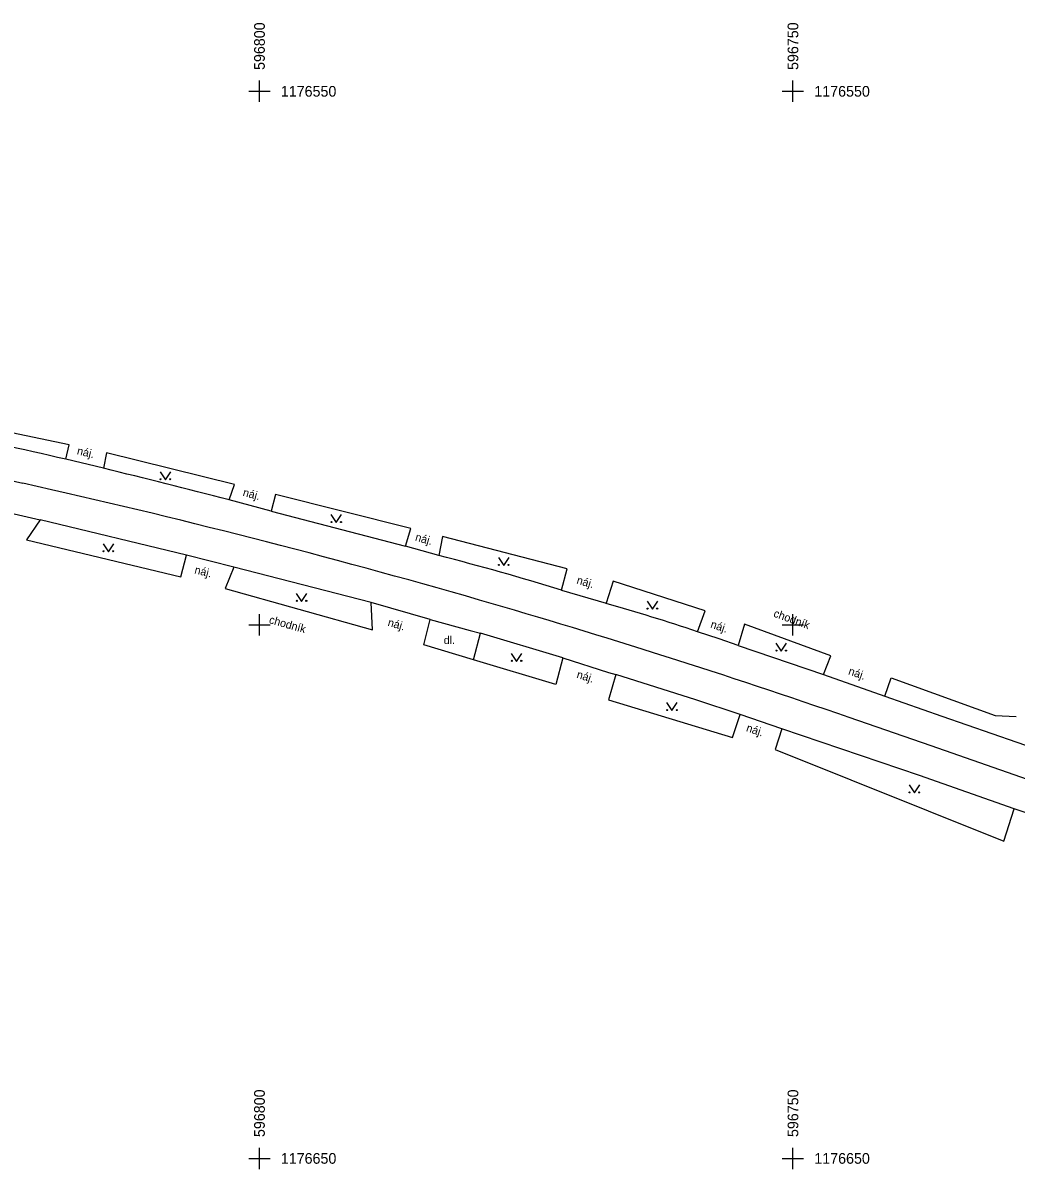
# Model space of a CAD drawing. Extents: x -598160 to -596067, y -1177005 to -1176344.
# Drawn here: x -596822.2 to -596729.1, y -1176651 to -1176543.6 of the extents above; entities that cross this region are included whole.
import ezdxf

# ---------------------------------------------------------------- set-up
doc = ezdxf.new("R2010")
doc.units = 0
for name, color, linetype in [('hektametrová síť', 7, 'Continuous'), ('obruba +0 cm', 7, 'Continuous'), ('obruba +12 cm', 7, 'Continuous'), ('obruba +3 cm', 7, 'Continuous'), ('popis ploch', 7, 'Continuous'), ('rozhraní ploch', 7, 'Continuous'), ('vodorovné značení', 7, 'Continuous'), ('zeleň', 7, 'Continuous')]:
    doc.layers.add(name, color=color, linetype=linetype)

msp = doc.modelspace()

# ---------------------------------------------------------------- linework, layer by layer
at = {"layer": 'hektametrová síť'}
for p, q in [((-596800, -1176551), (-596800, -1176549)), ((-596750, -1176551), (-596750, -1176549)), ((-596801, -1176550), (-596799, -1176550)), ((-596751, -1176550), (-596749, -1176550)), ((-596800, -1176601), (-596800, -1176599)), ((-596750, -1176601), (-596750, -1176599)), ((-596801, -1176600), (-596799, -1176600)), ((-596751, -1176600), (-596749, -1176600)), ((-596800, -1176651), (-596800, -1176649)), ((-596750, -1176651), (-596750, -1176649)), ((-596801, -1176650), (-596799, -1176650)), ((-596751, -1176650), (-596749, -1176650))]:
    msp.add_line(p, q, dxfattribs=at)
at = {"layer": 'obruba +0 cm'}
for p, q in [((-596814.63, -1176585.31), (-596818.16, -1176584.48)), ((-596798.9, -1176589.34), (-596802.85, -1176588.28)), ((-596823, -1176589.61), (-596820.54, -1176590.16)), ((-596783.18, -1176593.51), (-596786.32, -1176592.62)), ((-596802.39, -1176594.58), (-596806.83, -1176593.47)), ((-596784.01, -1176599.49), (-596789.54, -1176597.89)), ((-596771.57, -1176603.1), (-596767.28, -1176604.45)), ((-596767.28, -1176604.45), (-596766.59, -1176604.66)), ((-596747.13, -1176604.66), (-596741.39, -1176606.67))]:
    msp.add_line(p, q, dxfattribs=at)
at = {"layer": 'obruba +12 cm'}
for p, q in [((-596798.9, -1176589.34), (-596786.32, -1176592.62)), ((-596806.83, -1176593.47), (-596820.54, -1176590.16)), ((-596789.54, -1176597.89), (-596802.39, -1176594.58)), ((-596771.57, -1176603.1), (-596779.28, -1176600.79)), ((-596755.14, -1176601.93), (-596747.13, -1176604.66)), ((-596759.11, -1176607.03), (-596766.59, -1176604.66)), ((-596754.96, -1176608.39), (-596759.11, -1176607.03)), ((-596741.39, -1176606.67), (-596736.04, -1176608.55)), ((-596736.04, -1176608.55), (-596715.72, -1176615.6)), ((-596738.13, -1176614.11), (-596751.03, -1176609.73)), ((-596729.28, -1176617.25), (-596738.13, -1176614.11))]:
    msp.add_line(p, q, dxfattribs=at)
for centre, radius, start, end in [((-596922.01, -1177032.53), 459.93, 76.9505, 78.5161), ((-597174.08, -1178035.85), 1494.41, 75.61648, 76.08226), ((-596851.03, -1176856.68), 271.78, 73.0284, 75.5428), ((-596828.43, -1176808.89), 219.53, 71.5499, 73.8871)]:
    msp.add_arc(centre, radius, start, end, dxfattribs=at)
at = {"layer": 'obruba +3 cm'}
for p, q in [((-596771.7, -1176596.74), (-596767.5, -1176597.98)), ((-596784.01, -1176599.49), (-596780.26, -1176600.52)), ((-596780.26, -1176600.52), (-596779.28, -1176600.79)), ((-596756.93, -1176601.31), (-596758.95, -1176600.64)), ((-596755.14, -1176601.93), (-596756.93, -1176601.31)), ((-596751.03, -1176609.73), (-596754.96, -1176608.39)), ((-596725.43, -1176618.55), (-596729.28, -1176617.25))]:
    msp.add_line(p, q, dxfattribs=at)
at = {"layer": 'rozhraní ploch'}
for p, q in [((-596817.83, -1176583.12), (-596830.31, -1176580.53)), ((-596818.16, -1176584.48), (-596817.83, -1176583.12)), ((-596814.33, -1176583.89), (-596814.63, -1176585.31)), ((-596802.34, -1176586.85), (-596814.33, -1176583.89)), ((-596802.85, -1176588.28), (-596802.34, -1176586.85)), ((-596798.51, -1176587.79), (-596798.9, -1176589.34)), ((-596785.82, -1176590.97), (-596798.51, -1176587.79)), ((-596820.54, -1176590.16), (-596821.83, -1176592.03)), ((-596786.32, -1176592.62), (-596785.82, -1176590.97)), ((-596821.83, -1176592.03), (-596807.36, -1176595.51)), ((-596782.85, -1176591.72), (-596783.18, -1176593.51)), ((-596771.17, -1176594.75), (-596782.85, -1176591.72)), ((-596807.36, -1176595.51), (-596806.83, -1176593.47)), ((-596802.39, -1176594.58), (-596803.21, -1176596.6)), ((-596771.7, -1176596.74), (-596771.17, -1176594.75)), ((-596803.21, -1176596.6), (-596789.42, -1176600.46)), ((-596766.84, -1176595.92), (-596767.5, -1176597.98)), ((-596758.24, -1176598.7), (-596766.84, -1176595.92)), ((-596789.42, -1176600.46), (-596789.54, -1176597.89)), ((-596758.95, -1176600.64), (-596758.24, -1176598.7)), ((-596784.6, -1176601.86), (-596784.01, -1176599.49)), ((-596754.55, -1176599.95), (-596755.14, -1176601.93)), ((-596746.44, -1176602.91), (-596754.55, -1176599.95)), ((-596779.94, -1176603.28), (-596779.28, -1176600.79)), ((-596779.94, -1176603.28), (-596784.6, -1176601.86)), ((-596772.22, -1176605.6), (-596779.94, -1176603.28)), ((-596771.57, -1176603.1), (-596772.22, -1176605.6)), ((-596747.13, -1176604.66), (-596746.44, -1176602.91)), ((-596766.59, -1176604.66), (-596767.28, -1176607.02)), ((-596741.39, -1176606.67), (-596740.8, -1176604.95)), ((-596740.8, -1176604.95), (-596731.04, -1176608.48)), ((-596767.28, -1176607.02), (-596755.66, -1176610.56)), ((-596755.66, -1176610.56), (-596754.96, -1176608.39)), ((-596731.04, -1176608.48), (-596729.09, -1176608.58)), ((-596751.03, -1176609.73), (-596751.68, -1176611.67)), ((-596751.68, -1176611.67), (-596730.24, -1176620.27)), ((-596730.24, -1176620.27), (-596729.28, -1176617.25))]:
    msp.add_line(p, q, dxfattribs=at)
at = {"layer": 'vodorovné značení'}
for p, q in [((-596737.04, -1176611.35), (-596744.73, -1176608.69)), ((-596717.1, -1176618.32), (-596737.04, -1176611.35))]:
    msp.add_line(p, q, dxfattribs=at)
for centre, radius, start, end in [((-596901.54, -1176959.2), 380.82, 77.9709, 84.759), ((-596979.94, -1177293.15), 723.82, 73.91306, 77.41048), ((-596971.93, -1177263.5), 693.11, 70.86511, 73.87014)]:
    msp.add_arc(centre, radius, start, end, dxfattribs=at)
at = {"layer": 'zeleň'}
for points in [[(-596809.32, -1176585.65), (-596808.82, -1176586.4), (-596808.32, -1176585.65)], [(-596793.31, -1176589.67), (-596792.81, -1176590.42), (-596792.31, -1176589.67)], [(-596814.66, -1176592.4), (-596814.16, -1176593.15), (-596813.66, -1176592.4)], [(-596777.61, -1176593.68), (-596777.11, -1176594.43), (-596776.61, -1176593.68)], [(-596796.56, -1176597.05), (-596796.06, -1176597.8), (-596795.56, -1176597.05)], [(-596763.68, -1176597.78), (-596763.18, -1176598.53), (-596762.68, -1176597.78)], [(-596751.6, -1176601.71), (-596751.1, -1176602.46), (-596750.6, -1176601.71)], [(-596776.41, -1176602.67), (-596775.91, -1176603.42), (-596775.41, -1176602.67)], [(-596761.84, -1176607.29), (-596761.34, -1176608.04), (-596760.84, -1176607.29)], [(-596739.12, -1176615), (-596738.62, -1176615.75), (-596738.12, -1176615)]]:
    msp.add_lwpolyline(points, dxfattribs=at)
for centre in [(-596809.27, -1176586.35), (-596808.37, -1176586.35), (-596793.26, -1176590.37), (-596792.36, -1176590.37), (-596814.61, -1176593.1), (-596813.71, -1176593.1), (-596777.56, -1176594.38), (-596776.66, -1176594.38), (-596796.51, -1176597.75), (-596795.61, -1176597.75), (-596763.63, -1176598.48), (-596762.73, -1176598.48), (-596776.36, -1176603.37), (-596775.46, -1176603.37), (-596751.55, -1176602.41), (-596750.65, -1176602.41), (-596761.79, -1176607.99), (-596760.89, -1176607.99), (-596739.07, -1176615.7), (-596738.17, -1176615.7)]:
    msp.add_circle(centre, 0.05, dxfattribs=at)

# ---------------------------------------------------------------- texts
at = {"layer": 'hektametrová síť'}
for s, p in [('596800', (-596799.5, -1176548)), ('596750', (-596749.5, -1176548)), ('596800', (-596799.5, -1176648)), ('596750', (-596749.5, -1176648))]:
    msp.add_text(s, height=1, rotation=90, dxfattribs=at).set_placement(p)
for s, p in [('1176550', (-596798, -1176550.5)), ('1176550', (-596748, -1176550.5)), ('1176650', (-596798, -1176650.5)), ('1176650', (-596748, -1176650.5))]:
    msp.add_text(s, height=1, dxfattribs=at).set_placement(p)
at = {"layer": 'popis ploch'}
for s, rotation, p in [('náj.', 346.7685, (-596817.15, -1176584.01)), ('náj.', 344.9783, (-596801.61, -1176587.9)), ('náj.', 344.1752, (-596785.46, -1176592.09)), ('náj.', 345.9638, (-596806.14, -1176595.17)), ('náj.', 343.5514, (-596770.33, -1176596.12)), ('chodník', 339.9489, (-596751.89, -1176599.21)), ('chodník', 344.3624, (-596799.16, -1176599.83)), ('náj.', 343.8632, (-596788.03, -1176600.08)), ('náj.', 341.2948, (-596757.79, -1176600.24)), ('náj.', 342.532, (-596770.33, -1176604.95)), ('náj.', 340.7011, (-596744.87, -1176604.63)), ('náj.', 341.1723, (-596754.44, -1176609.95))]:
    msp.add_text(s, height=0.75, rotation=rotation, dxfattribs=at).set_placement(p)
msp.add_text('dl.', height=0.75, dxfattribs=at).set_placement((-596782.73, -1176601.8))

doc.saveas('drawing.dxf')
